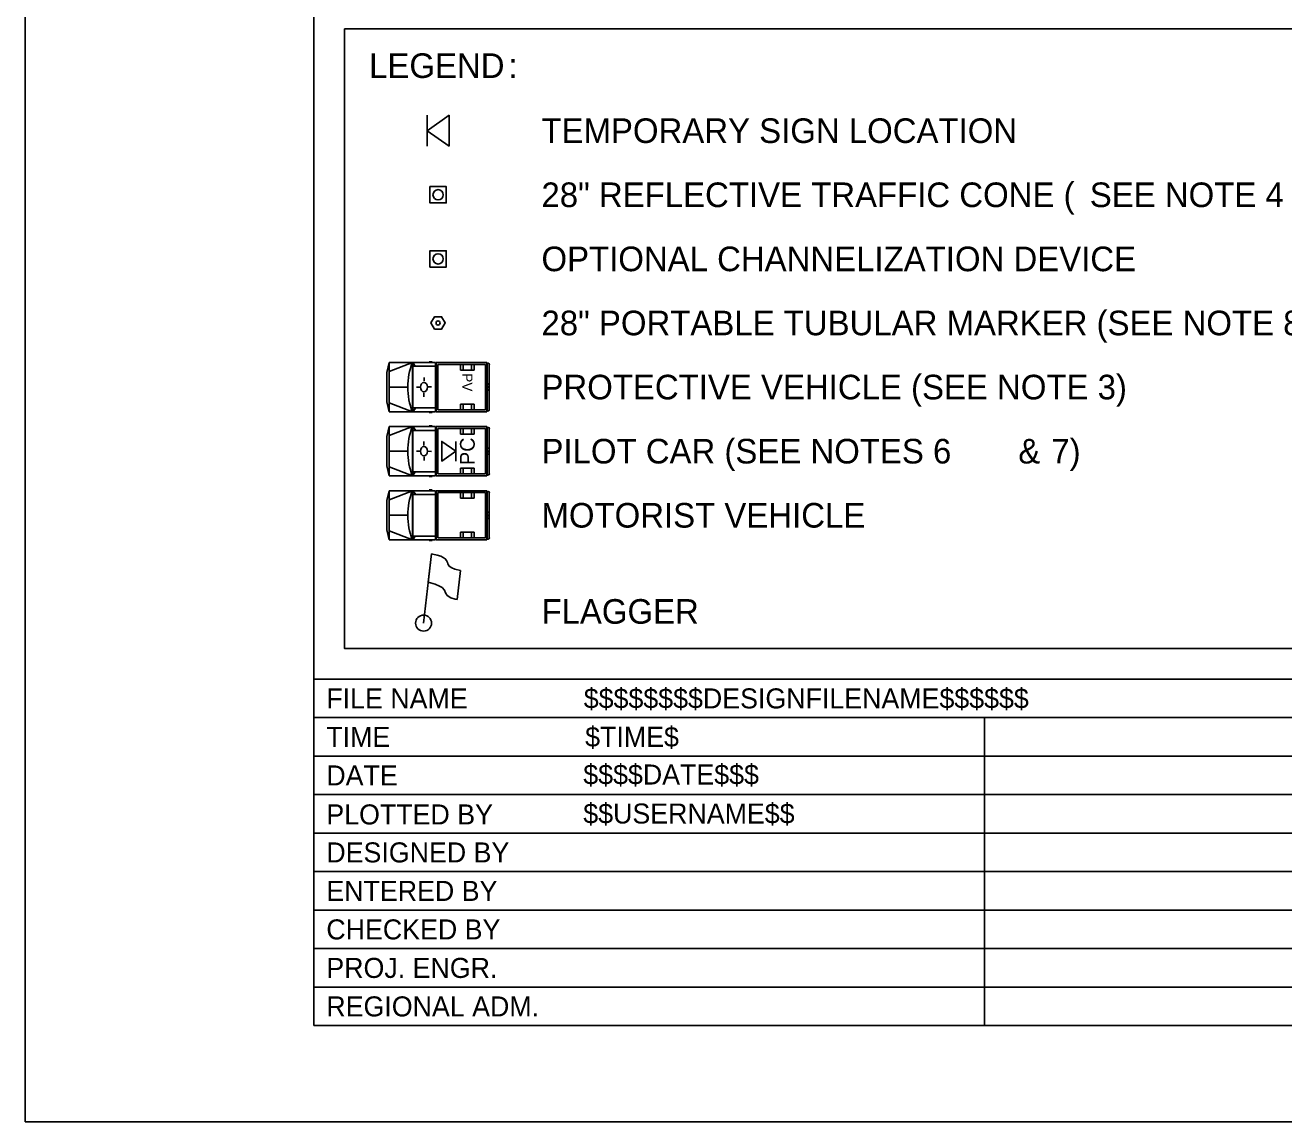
# Model space of a CAD drawing. Extents: x 99999.1 to 100095.7, y 99995 to 100010.7.
# Drawn here: x 100039.062 to 100043.152, y 99999.687 to 100003.251 of the extents above; entities that cross this region are included whole.
import ezdxf

# ---------------------------------------------------------------- set-up
doc = ezdxf.new("R2010")
doc.units = 0
for name, color, linetype in [('SH_GI_PlotLimits', 7, 'Continuous'), ('SH_GI_SheetBorder', 7, 'Continuous'), ('SH_GI_SheetTextInCells', 7, 'Continuous'), ('SH_GI_TitleBlockText', 7, 'Continuous'), ('TR_WZ_FlaggingStation', 7, 'Continuous'), ('TR_WZ_MotoristVehicle', 7, 'Continuous'), ('TR_WZ_PortableSignMountBlk-Org', 7, 'Continuous'), ('TR_WZ_PortableSignMountBlk-Wht', 7, 'Continuous'), ('TR_WZ_ProtectiveVehicle', 7, 'Continuous'), ('TR_WZ_TrafficCone', 7, 'Continuous'), ('TR_WZ_TubularMarker', 7, 'Continuous'), ('TR_WZ_WorkZoneTextCurrent', 7, 'Continuous')]:
    doc.layers.add(name, color=color, linetype=linetype)

msp = doc.modelspace()

# ---------------------------------------------------------------- linework, layer by layer
at = {"layer": 'SH_GI_PlotLimits'}
msp.add_lwpolyline([(100039.0625, 99999.6875), (100056.0625, 99999.6875), (100056.0625, 100010.6875), (100039.0625, 100010.6875)], close=True, dxfattribs=at)
at = {"layer": 'SH_GI_SheetBorder'}
for p, q in [((100040, 100010.375), (100040, 100000)), ((100040, 100001.1259), (100055.75, 100001.1259)), ((100040, 100001.0008), (100047.4566, 100001.0008)), ((100042.179, 100001.0008), (100042.179, 100000)), ((100040, 100000.8757), (100042.1821, 100000.8757)), ((100042.1821, 100000.8757), (100045.4466, 100000.8757)), ((100040, 100000.7506), (100042.1821, 100000.7506)), ((100042.1821, 100000.7506), (100045.4466, 100000.7506)), ((100040, 100000.6255), (100045.4466, 100000.6255)), ((100040, 100000.5004), (100045.4466, 100000.5004)), ((100040, 100000.3753), (100045.4466, 100000.3753)), ((100040, 100000.2502), (100045.4466, 100000.2502)), ((100040, 100000.1251), (100045.4466, 100000.1251)), ((100040, 100000), (100055.75, 100000))]:
    msp.add_line(p, q, dxfattribs=at)
at = {"layer": 'TR_WZ_FlaggingStation'}
for p, q in [((100040.3571, 100001.3079), (100040.3828, 100001.5327)), ((100040.3723, 100001.4414), (100040.3828, 100001.5329)), ((100040.4771, 100001.4786), (100040.4665, 100001.3849)), ((100040.3723, 100001.4414), (100040.3723, 100001.4414))]:
    msp.add_line(p, q, dxfattribs=at)
for points in [[(100040.3828, 100001.5329), (100040.3874, 100001.5319), (100040.4016, 100001.5291), (100040.4127, 100001.5258), (100040.4204, 100001.5209), (100040.4273, 100001.5171), (100040.4318, 100001.5117), (100040.4352, 100001.5054), (100040.4356, 100001.5005), (100040.4399, 100001.4931), (100040.4486, 100001.4871), (100040.4585, 100001.483), (100040.4771, 100001.4786)], [(100040.4665, 100001.3849), (100040.46, 100001.386), (100040.4458, 100001.3897), (100040.4333, 100001.3981), (100040.4281, 100001.4066), (100040.425, 100001.4148), (100040.4177, 100001.4235), (100040.4089, 100001.4285), (100040.395, 100001.4342), (100040.3723, 100001.4414)]]:
    msp.add_lwpolyline(points, dxfattribs=at)
msp.add_circle((100040.3571, 100001.3079), 0.026, dxfattribs=at)
at = {"layer": 'TR_WZ_MotoristVehicle'}
for p, q in [((100040.245, 100001.9466), (100040.2376, 100001.9143)), ((100040.245, 100001.9466), (100040.245, 100001.7866)), ((100040.245, 100001.9466), (100040.3962, 100001.9466)), ((100040.245, 100001.9173), (100040.3206, 100001.9466)), ((100040.3206, 100001.9466), (100040.3206, 100001.7866)), ((100040.322, 100001.9466), (100040.322, 100001.7866)), ((100040.322, 100001.9466), (100040.3316, 100001.9342)), ((100040.3756, 100001.9489), (100040.3846, 100001.9489)), ((100040.3962, 100001.9466), (100040.3962, 100001.7866)), ((100040.5629, 100001.9466), (100040.3984, 100001.9466)), ((100040.3984, 100001.9466), (100040.3984, 100001.7866)), ((100040.5583, 100001.9402), (100040.403, 100001.9402)), ((100040.403, 100001.9402), (100040.403, 100001.793)), ((100040.4772, 100001.9402), (100040.4772, 100001.9218)), ((100040.4852, 100001.9402), (100040.4852, 100001.9218)), ((100040.5124, 100001.9402), (100040.5124, 100001.9218)), ((100040.5212, 100001.9402), (100040.5212, 100001.9218)), ((100040.5583, 100001.9402), (100040.5583, 100001.793)), ((100040.5629, 100001.9466), (100040.5629, 100001.7866)), ((100040.5671, 100001.944), (100040.5635, 100001.944)), ((100040.5635, 100001.944), (100040.5635, 100001.7892)), ((100040.5706, 100001.9391), (100040.5706, 100001.7941)), ((100040.2376, 100001.9143), (100040.2376, 100001.8189)), ((100040.322, 100001.9342), (100040.3962, 100001.9342)), ((100040.3582, 100001.8983), (100040.3582, 100001.8854)), ((100040.5212, 100001.9218), (100040.4772, 100001.9218)), ((100040.245, 100001.8666), (100040.3058, 100001.8666)), ((100040.3341, 100001.8667), (100040.3442, 100001.8667)), ((100040.3695, 100001.8663), (100040.3695, 100001.8663)), ((100040.3829, 100001.866), (100040.371, 100001.8663)), ((100040.5706, 100001.8779), (100040.5635, 100001.8749)), ((100040.5706, 100001.8553), (100040.5635, 100001.8583)), ((100040.5687, 100001.8666), (100040.5654, 100001.8666)), ((100040.5671, 100001.8689), (100040.5671, 100001.8643)), ((100040.245, 100001.7866), (100040.2376, 100001.8189)), ((100040.245, 100001.8159), (100040.3206, 100001.7866)), ((100040.3588, 100001.8358), (100040.3586, 100001.8479)), ((100040.245, 100001.7866), (100040.3962, 100001.7866)), ((100040.322, 100001.799), (100040.3962, 100001.799)), ((100040.3299, 100001.799), (100040.322, 100001.7866)), ((100040.3756, 100001.7843), (100040.3846, 100001.7843)), ((100040.5629, 100001.7866), (100040.3984, 100001.7866)), ((100040.5583, 100001.793), (100040.403, 100001.793)), ((100040.4772, 100001.793), (100040.4772, 100001.8114)), ((100040.5212, 100001.8114), (100040.4772, 100001.8114)), ((100040.4852, 100001.793), (100040.4852, 100001.8114)), ((100040.5124, 100001.793), (100040.5124, 100001.8114)), ((100040.5212, 100001.793), (100040.5212, 100001.8114)), ((100040.5671, 100001.7892), (100040.5635, 100001.7892)), ((100040.245, 100001.7383), (100040.2376, 100001.706)), ((100040.245, 100001.7383), (100040.245, 100001.5783)), ((100040.245, 100001.7383), (100040.3962, 100001.7383)), ((100040.245, 100001.709), (100040.3206, 100001.7383)), ((100040.3206, 100001.7383), (100040.3206, 100001.5783)), ((100040.322, 100001.7383), (100040.322, 100001.5783)), ((100040.322, 100001.7383), (100040.3316, 100001.7259)), ((100040.3756, 100001.7406), (100040.3846, 100001.7406)), ((100040.3962, 100001.7383), (100040.3962, 100001.5783)), ((100040.5629, 100001.7383), (100040.3984, 100001.7383)), ((100040.3984, 100001.7383), (100040.3984, 100001.5783)), ((100040.5583, 100001.7319), (100040.403, 100001.7319)), ((100040.403, 100001.7319), (100040.403, 100001.5847)), ((100040.4772, 100001.7319), (100040.4772, 100001.7135)), ((100040.4852, 100001.7319), (100040.4852, 100001.7135)), ((100040.5124, 100001.7319), (100040.5124, 100001.7135)), ((100040.5212, 100001.7319), (100040.5212, 100001.7135)), ((100040.5583, 100001.7319), (100040.5583, 100001.5847)), ((100040.5629, 100001.7383), (100040.5629, 100001.5783)), ((100040.5671, 100001.7357), (100040.5635, 100001.7357)), ((100040.5635, 100001.7357), (100040.5635, 100001.581)), ((100040.5706, 100001.7308), (100040.5706, 100001.5858)), ((100040.2376, 100001.706), (100040.2376, 100001.6106)), ((100040.322, 100001.7259), (100040.3962, 100001.7259)), ((100040.5212, 100001.7135), (100040.4772, 100001.7135)), ((100040.245, 100001.6583), (100040.3058, 100001.6583)), ((100040.5706, 100001.6696), (100040.5635, 100001.6666)), ((100040.5706, 100001.6471), (100040.5635, 100001.6501)), ((100040.5687, 100001.6583), (100040.5654, 100001.6583)), ((100040.5671, 100001.6606), (100040.5671, 100001.6561)), ((100040.245, 100001.5783), (100040.2376, 100001.6106)), ((100040.245, 100001.6076), (100040.3206, 100001.5783)), ((100040.245, 100001.5783), (100040.3962, 100001.5783)), ((100040.322, 100001.5907), (100040.3962, 100001.5907)), ((100040.3299, 100001.5907), (100040.322, 100001.5783)), ((100040.3756, 100001.5761), (100040.3846, 100001.5761)), ((100040.5629, 100001.5783), (100040.3984, 100001.5783)), ((100040.5583, 100001.5847), (100040.403, 100001.5847)), ((100040.4772, 100001.5847), (100040.4772, 100001.6031)), ((100040.5212, 100001.6031), (100040.4772, 100001.6031)), ((100040.4852, 100001.5847), (100040.4852, 100001.6031)), ((100040.5124, 100001.5847), (100040.5124, 100001.6031)), ((100040.5212, 100001.5847), (100040.5212, 100001.6031)), ((100040.5671, 100001.581), (100040.5635, 100001.581))]:
    msp.add_line(p, q, dxfattribs=at)
for centre, major_axis, start_param, end_param in [((100040.4286, 100001.8666), (0, -0.1679), 4.215667, 5.208926), ((100040.5671, 100001.9391), (0, 0.00488), 4.712389, 6.283185), ((100040.5671, 100001.7941), (0, -0.00488), 0, 1.570796), ((100040.4286, 100001.6583), (0, -0.1679), 4.215667, 5.208926), ((100040.5671, 100001.7308), (0, 0.00488), 4.712389, 6.283185), ((100040.5671, 100001.5858), (0, -0.00488), 0, 1.570796)]:
    msp.add_ellipse(centre, major_axis=major_axis, ratio=0.73155, start_param=start_param, end_param=end_param, dxfattribs=at)
for centre, major_axis in [((100040.3582, 100001.8666), (0, 0.0154)), ((100040.5671, 100001.8666), (0, 0.00225)), ((100040.5671, 100001.6583), (0, 0.00225))]:
    msp.add_ellipse(centre, major_axis=major_axis, ratio=0.73155, dxfattribs=at)
at = {"layer": 'TR_WZ_PortableSignMountBlk-Org'}
msp.add_line((100040.3682, 100002.858), (100040.3682, 100002.958), dxfattribs=at)
msp.add_lwpolyline([(100040.3682, 100002.9079), (100040.44, 100002.958), (100040.44, 100002.858)], close=True, dxfattribs=at)
at = {"layer": 'TR_WZ_PortableSignMountBlk-Wht'}
msp.add_line((100040.4621, 100001.8985), (100040.4621, 100001.8345), dxfattribs=at)
msp.add_lwpolyline([(100040.4621, 100001.8666), (100040.4161, 100001.8345), (100040.4161, 100001.8985)], close=True, dxfattribs=at)
at = {"layer": 'TR_WZ_ProtectiveVehicle'}
for p, q in [((100040.245, 100002.1549), (100040.2376, 100002.1226)), ((100040.245, 100001.9949), (100040.245, 100002.1549)), ((100040.245, 100002.1549), (100040.3962, 100002.1549)), ((100040.245, 100002.1256), (100040.3206, 100002.1549)), ((100040.3206, 100001.9949), (100040.3206, 100002.1549)), ((100040.322, 100001.9949), (100040.322, 100002.1549)), ((100040.3299, 100002.1425), (100040.322, 100002.1549)), ((100040.322, 100002.1425), (100040.3962, 100002.1425)), ((100040.3756, 100002.1571), (100040.3846, 100002.1571)), ((100040.3962, 100001.9949), (100040.3962, 100002.1549)), ((100040.5629, 100002.1549), (100040.3984, 100002.1549)), ((100040.3984, 100001.9949), (100040.3984, 100002.1549)), ((100040.5583, 100002.1485), (100040.403, 100002.1485)), ((100040.403, 100002.0013), (100040.403, 100002.1485)), ((100040.4772, 100002.1485), (100040.4772, 100002.1301)), ((100040.4852, 100002.1485), (100040.4852, 100002.1301)), ((100040.5124, 100002.1485), (100040.5124, 100002.1301)), ((100040.5212, 100002.1485), (100040.5212, 100002.1301)), ((100040.5583, 100002.0013), (100040.5583, 100002.1485)), ((100040.5629, 100001.9949), (100040.5629, 100002.1549)), ((100040.5671, 100002.1523), (100040.5635, 100002.1523)), ((100040.5635, 100001.9975), (100040.5635, 100002.1523)), ((100040.5706, 100002.0024), (100040.5706, 100002.1474)), ((100040.2376, 100002.0272), (100040.2376, 100002.1226)), ((100040.3588, 100002.1057), (100040.3586, 100002.0936)), ((100040.5212, 100002.1301), (100040.4772, 100002.1301)), ((100040.245, 100002.0749), (100040.3058, 100002.0749)), ((100040.3341, 100002.0748), (100040.3442, 100002.0748)), ((100040.3695, 100002.0752), (100040.3695, 100002.0752)), ((100040.3829, 100002.0755), (100040.371, 100002.0752)), ((100040.5706, 100002.0862), (100040.5635, 100002.0831)), ((100040.5706, 100002.0636), (100040.5635, 100002.0666)), ((100040.5687, 100002.0749), (100040.5654, 100002.0749)), ((100040.5671, 100002.0726), (100040.5671, 100002.0771)), ((100040.245, 100001.9949), (100040.2376, 100002.0272)), ((100040.245, 100002.0242), (100040.3206, 100001.9949)), ((100040.3582, 100002.0432), (100040.3582, 100002.0561)), ((100040.5212, 100002.0197), (100040.4772, 100002.0197)), ((100040.4772, 100002.0013), (100040.4772, 100002.0197)), ((100040.4852, 100002.0013), (100040.4852, 100002.0197)), ((100040.5124, 100002.0013), (100040.5124, 100002.0197)), ((100040.5212, 100002.0013), (100040.5212, 100002.0197)), ((100040.245, 100001.9949), (100040.3962, 100001.9949)), ((100040.322, 100001.9949), (100040.3316, 100002.0073)), ((100040.322, 100002.0073), (100040.3962, 100002.0073)), ((100040.3756, 100001.9926), (100040.3846, 100001.9926)), ((100040.5629, 100001.9949), (100040.3984, 100001.9949)), ((100040.5583, 100002.0013), (100040.403, 100002.0013)), ((100040.5671, 100001.9975), (100040.5635, 100001.9975))]:
    msp.add_line(p, q, dxfattribs=at)
for centre, major_axis, start_param, end_param in [((100040.4286, 100002.0749), (0, -0.1679), 4.215852, 5.209111), ((100040.5671, 100002.1474), (0, 0.00488), 4.712389, 6.283185), ((100040.5671, 100002.0024), (0, -0.00488), 6.283185, 7.853982)]:
    msp.add_ellipse(centre, major_axis=major_axis, ratio=0.73155, start_param=start_param, end_param=end_param, dxfattribs=at)
for centre, major_axis in [((100040.3582, 100002.0749), (0, 0.0154)), ((100040.5671, 100002.0749), (0, 0.00225))]:
    msp.add_ellipse(centre, major_axis=major_axis, ratio=0.73155, dxfattribs=at)
at = {"layer": 'TR_WZ_TrafficCone'}
for points in [[(100040.3775, 100002.7264), (100040.4308, 100002.7264), (100040.4308, 100002.6731), (100040.3775, 100002.6731), (100040.3775, 100002.7264)], [(100040.3775, 100002.6731), (100040.4308, 100002.6731), (100040.4308, 100002.7264), (100040.3775, 100002.7264), (100040.3775, 100002.6731)], [(100040.3775, 100002.5181), (100040.4308, 100002.5181), (100040.4308, 100002.4648), (100040.3775, 100002.4648), (100040.3775, 100002.5181)], [(100040.3775, 100002.4648), (100040.4308, 100002.4648), (100040.4308, 100002.5181), (100040.3775, 100002.5181), (100040.3775, 100002.4648)]]:
    msp.add_lwpolyline(points, dxfattribs=at)
for centre in [(100040.4041, 100002.6997), (100040.4041, 100002.4914)]:
    msp.add_circle(centre, 0.0167, dxfattribs=at)
at = {"layer": 'TR_WZ_TubularMarker'}
msp.add_lwpolyline([(100040.381, 100002.2832), (100040.3926, 100002.3032), (100040.4157, 100002.3032), (100040.4272, 100002.2832), (100040.4157, 100002.2632), (100040.3926, 100002.2632)], close=True, dxfattribs=at)
msp.add_lwpolyline([(100040.3926, 100002.2632), (100040.4157, 100002.2632), (100040.4272, 100002.2832), (100040.4157, 100002.3032), (100040.3926, 100002.3032), (100040.381, 100002.2832), (100040.3926, 100002.2632)], dxfattribs=at)
msp.add_circle((100040.4041, 100002.2832), 0.00667, dxfattribs=at)
at = {"layer": 'TR_WZ_WorkZoneTextCurrent'}
msp.add_lwpolyline([(100040.1, 100003.2393), (100043.2886, 100003.2393), (100043.2886, 100001.2259), (100040.1, 100001.2259)], close=True, dxfattribs=at)

# ---------------------------------------------------------------- texts
at = {"layer": 'SH_GI_SheetTextInCells'}
for s, height, p in [('FILE NAME', 0.06505, (100040.041, 100001.0308)), ('TIME', 0.06505, (100040.041, 100000.9057)), ('DATE', 0.06505, (100040.041, 100000.7806)), ('PLOTTED BY', 0.06505, (100040.041, 100000.6538)), ('DESIGNED BY', 0.065052, (100040.041, 100000.5304)), ('ENTERED BY', 0.06505, (100040.041, 100000.4053)), ('CHECKED BY', 0.06505, (100040.041, 100000.2802)), ('PROJ. ENGR.', 0.065052, (100040.041, 100000.1551)), ('REGIONAL ADM.', 0.065052, (100040.041, 100000.03))]:
    msp.add_text(s, height=height, dxfattribs=at).set_placement(p)
at = {"layer": 'SH_GI_TitleBlockText'}
for s, height, p in [('$$$$$$$$DESIGNFILENAME$$$$$$', 0.065052, (100040.8775, 100001.0308)), ('$TIME$', 0.06505, (100040.882, 100000.9059)), ('$$$$DATE$$$', 0.065052, (100040.8759, 100000.7835)), ('$$USERNAME$$', 0.065052, (100040.8759, 100000.6567))]:
    msp.add_text(s, height=height, dxfattribs=at).set_placement(p)
at = {"layer": 'TR_WZ_MotoristVehicle'}
msp.add_text('PC', height=0.048, rotation=90, dxfattribs=at).set_placement((100040.5232, 100001.8218))
at = {"layer": 'TR_WZ_ProtectiveVehicle'}
msp.add_text('PV', height=0.0334, rotation=270, dxfattribs=at).set_placement((100040.4825, 100002.1202))
at = {"layer": 'TR_WZ_WorkZoneTextCurrent'}
for s, p in [('LEGEND', (100040.18, 100003.0793)), (':', (100040.6328, 100003.0793)), ('TEMPORARY SIGN LOCATION ', (100040.74, 100002.868)), ('28" REFLECTIVE TRAFFIC CONE (', (100040.74, 100002.6597)), ('SEE NOTE 4', (100042.5216, 100002.6597)), ('OPTIONAL CHANNELIZATION DEVICE', (100040.74, 100002.4514)), ('28" PORTABLE TUBULAR MARKER (SEE NOTE 8)', (100040.74, 100002.2432)), ('PROTECTIVE VEHICLE (SEE NOTE 3)', (100040.74, 100002.0349)), ('PILOT CAR (SEE NOTES 6', (100040.74, 100001.8266)), ('&', (100042.2894, 100001.8266)), ('7)', (100042.3966, 100001.8266)), ('MOTORIST VEHICLE', (100040.74, 100001.6183)), ('FLAGGER', (100040.74, 100001.3059))]:
    msp.add_text(s, height=0.08, rotation=360, dxfattribs=at).set_placement(p)

doc.saveas('drawing.dxf')
